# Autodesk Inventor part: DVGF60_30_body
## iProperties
Created: 2010-04
Part Number: DVGF60_30_body
Document SubType Name: Modeling
Designer: TB
Mass: 737.882 g
Surface Area: 1331.22 cm^2
Volume: 737.882 cm^3
Density: 1 g/cm^3
Author: TB
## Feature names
1. Kropp [Revolution]
2. Chamfer
3. Extrusion2
4. Hole1
5. Revolution2
6. Hole2
7. Fillet1
8. Extrusion3
9. Hole3
